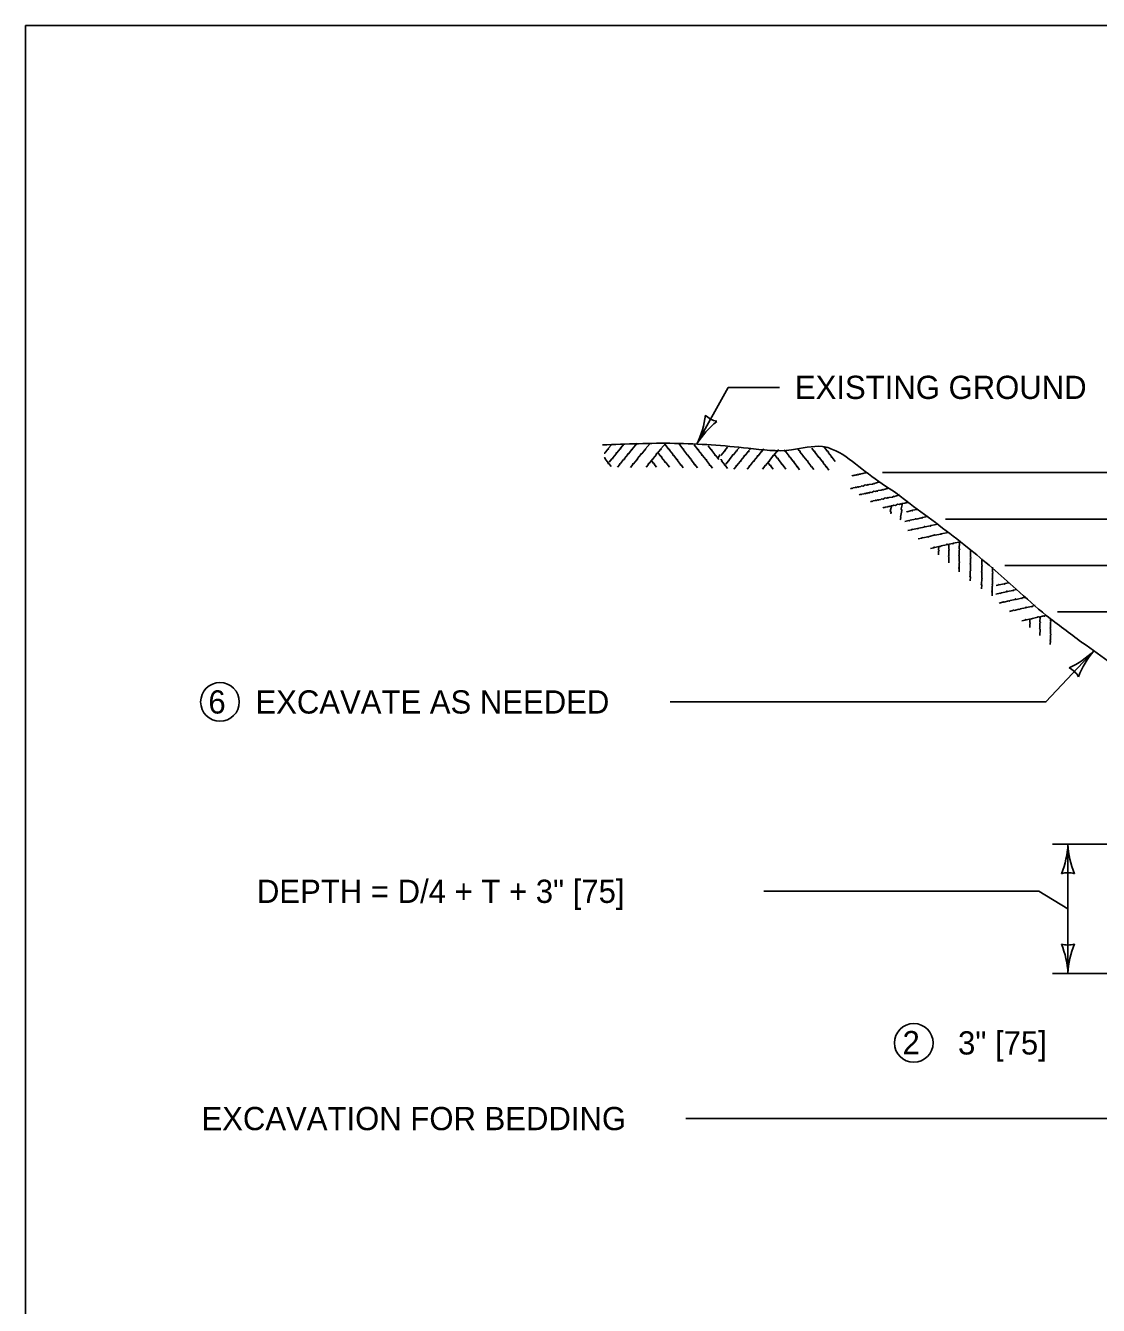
# Model space of a CAD drawing. Extents: x 49991.4 to 50021, y 49987.6 to 50011.4.
# Drawn here: x 49999.384 to 50002.154, y 49995.693 to 49998.999 of the extents above; entities that cross this region are included whole.
import ezdxf

# ---------------------------------------------------------------- set-up
doc = ezdxf.new("R2010")
doc.units = 0
for name, color, linetype in [('Level 1', 7, 'Continuous'), ('Level 2', 7, 'Continuous'), ('Level 3', 7, 'Continuous')]:
    doc.layers.add(name, color=color, linetype=linetype)

msp = doc.modelspace()

# ---------------------------------------------------------------- linework, layer by layer
at = {"layer": 'Level 1'}
for p, q in [((50001.5964, 49997.8446), (50003.795, 49997.8446)), ((50001.7594, 49997.7246), (50003.4766, 49997.7246)), ((50001.9129, 49997.6046), (50003.1822, 49997.6047)), ((50002.0489, 49997.4846), (50003.0064, 49997.4846))]:
    msp.add_line(p, q, dxfattribs=at)
msp.add_lwpolyline([(49999.3835, 49998.9992), (50016.7501, 49998.9992), (50016.7501, 49987.7988), (49999.3835, 49987.7988)], close=True, dxfattribs=at)
for points in [[(50000.8966, 49997.9164), (50000.8884, 49997.9068), (50000.8892, 49997.9052), (50000.8876, 49997.9052), (50000.8791, 49997.8947), (50000.878, 49997.8948)], [(50000.9298, 49997.9191), (50000.9198, 49997.9075), (50000.9206, 49997.9059), (50000.919, 49997.9059), (50000.9105, 49997.8954), (50000.9084, 49997.8955), (50000.9086, 49997.8934), (50000.8998, 49997.8829), (50000.8998, 49997.8808), (50000.8979, 49997.8802), (50000.891, 49997.8715)], [(50000.9626, 49997.9203), (50000.9499, 49997.9055), (50000.9507, 49997.9039), (50000.9491, 49997.9039), (50000.9406, 49997.8935), (50000.9384, 49997.8935), (50000.9387, 49997.8915), (50000.9299, 49997.8809), (50000.9299, 49997.8788), (50000.928, 49997.8782), (50000.9196, 49997.8677), (50000.9176, 49997.8676), (50000.918, 49997.8656), (50000.9119, 49997.8585)], [(50000.9963, 49997.9197), (50000.984, 49997.9052), (50000.9847, 49997.9036), (50000.9831, 49997.9037), (50000.9746, 49997.8932), (50000.9725, 49997.8932), (50000.9727, 49997.8912), (50000.9639, 49997.8806), (50000.9639, 49997.8786), (50000.962, 49997.8779), (50000.9537, 49997.8675), (50000.9517, 49997.8673), (50000.952, 49997.8653), (50000.946, 49997.8582)], [(50001.0366, 49997.9205), (50001.0239, 49997.9057), (50001.0246, 49997.904), (50001.023, 49997.9041), (50001.0145, 49997.8936), (50001.0124, 49997.8936), (50001.0126, 49997.8916), (50001.0039, 49997.881), (50001.0038, 49997.879), (50001.0019, 49997.8783), (50000.9936, 49997.8679), (50000.9915, 49997.8678), (50000.9919, 49997.8657), (50000.9859, 49997.8586)], [(50001.0817, 49997.857), (50001.0764, 49997.8643), (50001.0747, 49997.8639), (50001.0751, 49997.8654), (50001.0668, 49997.8761), (50001.0673, 49997.8781), (50001.0653, 49997.8784), (50001.0569, 49997.8893), (50001.055, 49997.8898), (50001.0548, 49997.8918), (50001.0465, 49997.9023), (50001.0468, 49997.9043), (50001.0448, 49997.9044), (50001.0353, 49997.917)], [(50001.1185, 49997.8571), (50001.1123, 49997.8654), (50001.1106, 49997.865), (50001.111, 49997.8666), (50001.1027, 49997.8772), (50001.1032, 49997.8793), (50001.1012, 49997.8795), (50001.0928, 49997.8905), (50001.0909, 49997.891), (50001.0907, 49997.8929), (50001.0824, 49997.9035), (50001.0827, 49997.9055), (50001.0807, 49997.9056), (50001.0703, 49997.9194)], [(50001.1574, 49997.8557), (50001.1512, 49997.864), (50001.1495, 49997.8636), (50001.1499, 49997.8651), (50001.1416, 49997.8758), (50001.1421, 49997.8779), (50001.1401, 49997.8781), (50001.1318, 49997.889), (50001.1298, 49997.8895), (50001.1296, 49997.8915), (50001.1213, 49997.902), (50001.1216, 49997.904), (50001.1196, 49997.9041), (50001.1104, 49997.9164)], [(50001.1737, 49997.8784), (50001.1659, 49997.8886), (50001.164, 49997.8891), (50001.1638, 49997.8911), (50001.1555, 49997.9016), (50001.1558, 49997.9036), (50001.1537, 49997.9037), (50001.146, 49997.9141)], [(50001.1961, 49997.9099), (50001.1893, 49997.9019), (50001.1901, 49997.9003), (50001.1884, 49997.9003), (50001.18, 49997.8898), (50001.1788, 49997.8899)], [(50001.226, 49997.9088), (50001.2207, 49997.9026), (50001.2215, 49997.901), (50001.2199, 49997.901), (50001.2114, 49997.8905), (50001.2092, 49997.8906), (50001.2095, 49997.8885), (50001.2007, 49997.878), (50001.2007, 49997.8759), (50001.1988, 49997.8753), (50001.1919, 49997.8666)], [(50001.2555, 49997.9061), (50001.2508, 49997.9006), (50001.2516, 49997.899), (50001.25, 49997.899), (50001.2415, 49997.8886), (50001.2393, 49997.8886), (50001.2396, 49997.8866), (50001.2308, 49997.876), (50001.2308, 49997.8739), (50001.2289, 49997.8733), (50001.2205, 49997.8628), (50001.2185, 49997.8627), (50001.2188, 49997.8607), (50001.2128, 49997.8536)], [(50001.2897, 49997.906), (50001.2848, 49997.9003), (50001.2856, 49997.8987), (50001.284, 49997.8988), (50001.2755, 49997.8883), (50001.2734, 49997.8883), (50001.2736, 49997.8863), (50001.2648, 49997.8757), (50001.2648, 49997.8737), (50001.2629, 49997.873), (50001.2546, 49997.8626), (50001.2525, 49997.8625), (50001.2529, 49997.8604), (50001.2469, 49997.8533)], [(50001.3277, 49997.9042), (50001.3248, 49997.9008), (50001.3255, 49997.8991), (50001.3239, 49997.8992), (50001.3154, 49997.8887), (50001.3133, 49997.8887), (50001.3135, 49997.8867), (50001.3047, 49997.8761), (50001.3047, 49997.8741), (50001.3028, 49997.8734), (50001.2945, 49997.863), (50001.2924, 49997.8629), (50001.2928, 49997.8608), (50001.2868, 49997.8537)], [(50001.3826, 49997.8521), (50001.3773, 49997.8594), (50001.3756, 49997.859), (50001.376, 49997.8605), (50001.3677, 49997.8712), (50001.3682, 49997.8733), (50001.3662, 49997.8735), (50001.3578, 49997.8844), (50001.3559, 49997.8849), (50001.3557, 49997.8869), (50001.3474, 49997.8974), (50001.3477, 49997.8994), (50001.3456, 49997.8995), (50001.3425, 49997.9037)], [(50001.4193, 49997.8522), (50001.4132, 49997.8605), (50001.4115, 49997.8601), (50001.4119, 49997.8617), (50001.4036, 49997.8723), (50001.4041, 49997.8744), (50001.4021, 49997.8746), (50001.3937, 49997.8856), (50001.3918, 49997.8861), (50001.3916, 49997.888), (50001.3833, 49997.8986), (50001.3836, 49997.9006), (50001.3815, 49997.9007), (50001.379, 49997.9041)], [(50001.4582, 49997.8508), (50001.4521, 49997.8591), (50001.4504, 49997.8587), (50001.4508, 49997.8602), (50001.4425, 49997.8709), (50001.443, 49997.873), (50001.441, 49997.8732), (50001.4326, 49997.8841), (50001.4307, 49997.8846), (50001.4305, 49997.8866), (50001.4222, 49997.8971), (50001.4225, 49997.8991), (50001.4205, 49997.8992), (50001.4138, 49997.9081)], [(50001.4746, 49997.8735), (50001.4668, 49997.8837), (50001.4648, 49997.8842), (50001.4647, 49997.8862), (50001.4564, 49997.8967), (50001.4567, 49997.8987), (50001.4546, 49997.8988), (50001.4449, 49997.9118)], [(50000.8956, 49997.8602), (50000.8896, 49997.8684), (50000.8878, 49997.868), (50000.8882, 49997.8695), (50000.8799, 49997.8802), (50000.8805, 49997.8823), (50000.8784, 49997.8825), (50000.8779, 49997.8832)], [(50001.0129, 49997.8586), (50001.007, 49997.8661), (50001.0074, 49997.8681), (50001.0053, 49997.8682), (50000.9996, 49997.8758)], [(50001.0462, 49997.8586), (50001.0367, 49997.871), (50001.0348, 49997.8715), (50001.0346, 49997.8734), (50001.0262, 49997.884), (50001.0266, 49997.8859), (50001.0245, 49997.886), (50001.0167, 49997.8965)], [(50001.1765, 49997.8899), (50001.1754, 49997.8899), (50001.1756, 49997.8879), (50001.1724, 49997.8839)], [(50001.1965, 49997.8553), (50001.1905, 49997.8635), (50001.1887, 49997.8631), (50001.1891, 49997.8646), (50001.1808, 49997.8753), (50001.1814, 49997.8774), (50001.1793, 49997.8776), (50001.1788, 49997.8783)], [(50001.3138, 49997.8537), (50001.3079, 49997.8612), (50001.3082, 49997.8632), (50001.3062, 49997.8633), (50001.3005, 49997.8709)], [(50001.3471, 49997.8537), (50001.3376, 49997.8661), (50001.3357, 49997.8666), (50001.3354, 49997.8685), (50001.3271, 49997.8791), (50001.3275, 49997.8811), (50001.3254, 49997.8811), (50001.318, 49997.8911)], [(50001.5539, 49997.8457), (50001.554, 49997.8443), (50001.5494, 49997.8431), (50001.5487, 49997.8423), (50001.548, 49997.8429), (50001.546, 49997.842), (50001.5419, 49997.8415), (50001.5413, 49997.8408), (50001.5405, 49997.8414), (50001.5386, 49997.8405), (50001.5364, 49997.8409), (50001.5339, 49997.8392), (50001.5317, 49997.8397), (50001.5311, 49997.8389), (50001.5284, 49997.8386), (50001.5278, 49997.8378), (50001.527, 49997.8384), (50001.525, 49997.8375), (50001.5242, 49997.8381), (50001.5236, 49997.8374), (50001.5209, 49997.8371), (50001.5203, 49997.8363), (50001.5195, 49997.8369), (50001.5176, 49997.836)], [(50001.5864, 49997.8224), (50001.5867, 49997.8197), (50001.5773, 49997.8172), (50001.5761, 49997.8157), (50001.5746, 49997.8168), (50001.5706, 49997.8151), (50001.5624, 49997.8141), (50001.5612, 49997.8126), (50001.5596, 49997.8138), (50001.5557, 49997.8119), (50001.5514, 49997.8128), (50001.5463, 49997.8095), (50001.542, 49997.8103), (50001.5408, 49997.8089), (50001.5353, 49997.8082), (50001.5341, 49997.8067), (50001.5326, 49997.8079), (50001.5287, 49997.806), (50001.5271, 49997.8072), (50001.5259, 49997.8057), (50001.5204, 49997.8051), (50001.5193, 49997.8036), (50001.5177, 49997.8048), (50001.5137, 49997.8029)], [(50001.609, 49997.8063), (50001.6093, 49997.8035), (50001.5999, 49997.8011), (50001.5987, 49997.7996), (50001.5972, 49997.8008), (50001.5932, 49997.7989), (50001.585, 49997.798), (50001.5838, 49997.7964), (50001.5823, 49997.7977), (50001.5783, 49997.7958), (50001.5741, 49997.7967), (50001.5689, 49997.7933), (50001.5647, 49997.7942), (50001.5635, 49997.7927), (50001.558, 49997.7921), (50001.5568, 49997.7906), (50001.5552, 49997.7918), (50001.5513, 49997.7899), (50001.5497, 49997.7912), (50001.5485, 49997.7896), (50001.5431, 49997.789), (50001.5419, 49997.7875), (50001.5403, 49997.7887), (50001.5364, 49997.7868)], [(50001.638, 49997.7889), (50001.6384, 49997.7861), (50001.6289, 49997.7837), (50001.6277, 49997.7821), (50001.6262, 49997.7833), (50001.6223, 49997.7815), (50001.6141, 49997.7806), (50001.6129, 49997.779), (50001.6113, 49997.7802), (50001.6074, 49997.7784), (50001.6031, 49997.7793), (50001.5979, 49997.7759), (50001.5937, 49997.7768), (50001.5925, 49997.7753), (50001.587, 49997.7746), (50001.5858, 49997.7731), (50001.5843, 49997.7744), (50001.5803, 49997.7725), (50001.5788, 49997.7737), (50001.5776, 49997.7722), (50001.5721, 49997.7715), (50001.5709, 49997.77), (50001.5694, 49997.7712), (50001.5654, 49997.7694)], [(50001.6135, 49997.8034), (50001.6277, 49997.7946), (50001.6676, 49997.7639)], [(50001.6623, 49997.768), (50001.6623, 49997.768), (50001.661, 49997.7676), (50001.6597, 49997.766), (50001.6582, 49997.7673), (50001.6543, 49997.7654), (50001.6461, 49997.7645), (50001.6449, 49997.7629), (50001.6433, 49997.7642), (50001.6394, 49997.7623), (50001.6351, 49997.7632), (50001.6299, 49997.7598), (50001.6257, 49997.7607), (50001.6245, 49997.7592), (50001.619, 49997.7586), (50001.6178, 49997.7571), (50001.6163, 49997.7583), (50001.6123, 49997.7565), (50001.6108, 49997.7576), (50001.6096, 49997.7561), (50001.6041, 49997.7555), (50001.6029, 49997.754), (50001.6014, 49997.7552), (50001.5974, 49997.7533)], [(50001.6206, 49997.7598), (50001.6167, 49997.7455), (50001.6186, 49997.7415), (50001.6178, 49997.7382)], [(50001.6484, 49997.7651), (50001.6445, 49997.7508), (50001.6463, 49997.7468), (50001.6428, 49997.7298), (50001.6443, 49997.7286), (50001.6434, 49997.7243), (50001.6424, 49997.723)], [(50001.6863, 49997.7496), (50001.6739, 49997.7472), (50001.6735, 49997.7455), (50001.6723, 49997.7465), (50001.6591, 49997.7435), (50001.6583, 49997.7443)], [(50001.714, 49997.7311), (50001.6989, 49997.7282), (50001.6986, 49997.7265), (50001.6973, 49997.7275), (50001.6841, 49997.7246), (50001.6826, 49997.7259), (50001.6814, 49997.7242), (50001.668, 49997.7214), (50001.6667, 49997.7198), (50001.6648, 49997.7205), (50001.654, 49997.7179)], [(50001.7404, 49997.7117), (50001.7213, 49997.708), (50001.7209, 49997.7062), (50001.7197, 49997.7072), (50001.7065, 49997.7044), (50001.7048, 49997.7057), (50001.7038, 49997.704), (50001.6903, 49997.7011), (50001.689, 49997.6995), (50001.6872, 49997.7002), (50001.674, 49997.6972), (50001.6724, 49997.6984), (50001.6715, 49997.6965), (50001.6623, 49997.6948)], [(50001.7665, 49997.6903), (50001.7478, 49997.6865), (50001.7474, 49997.6849), (50001.7462, 49997.6859), (50001.733, 49997.683), (50001.7313, 49997.6843), (50001.7303, 49997.6826), (50001.7168, 49997.6798), (50001.7155, 49997.6782), (50001.7136, 49997.6788), (50001.7006, 49997.6758), (50001.6989, 49997.6769), (50001.6979, 49997.6752), (50001.6888, 49997.6733)], [(50001.7985, 49997.6658), (50001.7794, 49997.6621), (50001.7789, 49997.6604), (50001.7777, 49997.6614), (50001.7645, 49997.6585), (50001.7628, 49997.6598), (50001.7618, 49997.6581), (50001.7484, 49997.6552), (50001.747, 49997.6537), (50001.7451, 49997.6543), (50001.7321, 49997.6514), (50001.7304, 49997.6526), (50001.7294, 49997.6507), (50001.7203, 49997.6489)], [(50001.7415, 49997.6321), (50001.7415, 49997.6416), (50001.7431, 49997.6429), (50001.7415, 49997.6443), (50001.7418, 49997.6538)], [(50001.7676, 49997.6114), (50001.7678, 49997.627), (50001.7667, 49997.6286), (50001.7677, 49997.6302), (50001.7677, 49997.6437), (50001.7692, 49997.6449), (50001.7676, 49997.6463), (50001.768, 49997.6594)], [(50001.7944, 49997.5881), (50001.7948, 49997.5971), (50001.7932, 49997.5978), (50001.7944, 49997.5987), (50001.7946, 49997.6123), (50001.7962, 49997.6135), (50001.7948, 49997.615), (50001.795, 49997.6288), (50001.7939, 49997.6304), (50001.7949, 49997.632), (50001.795, 49997.6454), (50001.7964, 49997.6468), (50001.7949, 49997.6481), (50001.7953, 49997.6639)], [(50001.8233, 49997.5653), (50001.8236, 49997.5756), (50001.822, 49997.5764), (50001.8233, 49997.5774), (50001.8234, 49997.5908), (50001.8251, 49997.5922), (50001.8236, 49997.5936), (50001.8239, 49997.6074), (50001.8227, 49997.609), (50001.8237, 49997.6106), (50001.8238, 49997.6241), (50001.8253, 49997.6254), (50001.8238, 49997.6268), (50001.8242, 49997.644)], [(50001.8525, 49997.5447), (50001.8528, 49997.5551), (50001.8513, 49997.5558), (50001.8525, 49997.5567), (50001.8527, 49997.5703), (50001.8544, 49997.5716), (50001.8529, 49997.573), (50001.8532, 49997.5867), (50001.8519, 49997.5883), (50001.853, 49997.59), (50001.853, 49997.6034), (50001.8545, 49997.6048), (50001.853, 49997.6061), (50001.8534, 49997.6215)], [(50001.8803, 49997.5552), (50001.8806, 49997.5681), (50001.8794, 49997.5697), (50001.8805, 49997.5713), (50001.8805, 49997.5847), (50001.882, 49997.5861), (50001.8804, 49997.5875), (50001.8808, 49997.6004)], [(50001.8796, 49997.5267), (50001.88, 49997.5368), (50001.8783, 49997.5376), (50001.8796, 49997.5386), (50001.8797, 49997.5521), (50001.8815, 49997.5534), (50001.88, 49997.5548), (50001.88, 49997.5557)], [(50001.9426, 49997.5427), (50001.9346, 49997.5411), (50001.9342, 49997.5394), (50001.9329, 49997.5403), (50001.9198, 49997.5374), (50001.9181, 49997.5388), (50001.917, 49997.537), (50001.9036, 49997.5343), (50001.9023, 49997.5326), (50001.9004, 49997.5333), (50001.8896, 49997.5308)], [(50001.8971, 49997.5552), (50001.8962, 49997.5558), (50001.8951, 49997.5542), (50001.8901, 49997.553)], [(50001.9229, 49997.5602), (50001.9126, 49997.5582), (50001.9122, 49997.5564), (50001.9109, 49997.5575), (50001.8978, 49997.5545), (50001.8969, 49997.5553)], [(50001.964, 49997.5222), (50001.9569, 49997.5208), (50001.9565, 49997.5191), (50001.9553, 49997.5201), (50001.9422, 49997.5172), (50001.9404, 49997.5186), (50001.9394, 49997.5168), (50001.9259, 49997.514), (50001.9246, 49997.5123), (50001.9228, 49997.5131), (50001.9097, 49997.51), (50001.908, 49997.5112), (50001.907, 49997.5095), (50001.8979, 49997.5076)], [(50001.9907, 49997.5009), (50001.9833, 49997.4995), (50001.983, 49997.4977), (50001.9818, 49997.4988), (50001.9686, 49997.4958), (50001.967, 49997.4971), (50001.9659, 49997.4955), (50001.9524, 49997.4926), (50001.9511, 49997.4911), (50001.9492, 49997.4917), (50001.9363, 49997.4887), (50001.9346, 49997.4899), (50001.9336, 49997.488), (50001.9244, 49997.4862)], [(50002.0194, 49997.4759), (50002.015, 49997.475), (50002.0145, 49997.4732), (50002.0133, 49997.4743), (50002.0001, 49997.4714), (50001.9985, 49997.4727), (50001.9974, 49997.471), (50001.9839, 49997.4681), (50001.9827, 49997.4666), (50001.9807, 49997.4672), (50001.9678, 49997.4642), (50001.9661, 49997.4654), (50001.9651, 49997.4635), (50001.956, 49997.4617)], [(50001.9771, 49997.4449), (50001.9771, 49997.4545), (50001.9786, 49997.4559), (50001.9771, 49997.4572), (50001.9774, 49997.4667)], [(50002.0032, 49997.4242), (50002.0035, 49997.4399), (50002.0023, 49997.4414), (50002.0032, 49997.4431), (50002.0033, 49997.4566), (50002.0049, 49997.4579), (50002.0032, 49997.4592), (50002.0036, 49997.4716)], [(50002.03, 49997.4009), (50002.0304, 49997.4099), (50002.0288, 49997.4107), (50002.0301, 49997.4116), (50002.0302, 49997.4251), (50002.0319, 49997.4265), (50002.0305, 49997.4279), (50002.0307, 49997.4416), (50002.0295, 49997.4432), (50002.0306, 49997.4449), (50002.0306, 49997.4583), (50002.0321, 49997.4597), (50002.0305, 49997.461), (50002.0307, 49997.4663)]]:
    msp.add_lwpolyline(points, dxfattribs=at)
for points in [[(50000.8731, 49997.9159), (50001.0592, 49997.9201), (50001.2495, 49997.9075), (50001.3616, 49997.9032), (50001.442, 49997.9117), (50001.4759, 49997.9011), (50001.5432, 49997.8542), (50001.6135, 49997.8034)], [(50001.6676, 49997.7639), (50001.816, 49997.6515), (50001.9419, 49997.5436), (50002.0197, 49997.4756), (50002.1106, 49997.407), (50002.113, 49997.4052)], [(50002.113, 49997.4052), (50002.2614, 49997.2928), (50002.2697, 49997.2855)]]:
    msp.add_spline(points, degree=3, dxfattribs=at)
at = {"layer": 'Level 2'}
for centre in [(49999.8855, 49997.2522), (50001.6774, 49996.3715)]:
    msp.add_circle(centre, 0.05, dxfattribs=at)
at = {"layer": 'Level 3'}
for p, q in [((50001.1171, 49997.9186), (50001.1982, 49998.0648)), ((50001.3304, 49998.0648), (50001.1982, 49998.0648)), ((50001.1982, 49998.0648), (50001.3304, 49998.0648)), ((50002.0355, 49996.8846), (50002.3003, 49996.8846)), ((50002.0755, 49996.5509), (50002.0755, 49996.8846)), ((50002.0007, 49996.7631), (50001.2905, 49996.7631)), ((50002.0755, 49996.7178), (50002.0007, 49996.7631)), ((50002.0355, 49996.5509), (50002.8589, 49996.5509)), ((50002.6251, 49996.1761), (50001.0883, 49996.1761))]:
    msp.add_line(p, q, dxfattribs=at)
msp.add_lwpolyline([(50001.0483, 49997.2522), (50002.0187, 49997.2522), (50002.1426, 49997.3844)], dxfattribs=at)
for centre, radius, start, end in [((50000.9184, 49998.0184), 0.2223, 333.3425, 353.526), ((50001.315, 49997.7957), 0.233, 128.9048, 148.1547), ((50001.1793, 49998.0308), 0.0548, 223.1208, 258.8432), ((50001.9868, 49997.543), 0.2223, 294.3067, 314.4902), ((50002.3203, 49997.2336), 0.233, 139.678, 158.9279), ((50002.0549, 49997.2908), 0.0548, 28.9895, 64.7119), ((50001.8534, 49996.8938), 0.2223, 337.456, 357.6395), ((50002.3082, 49996.8961), 0.233, 182.8273, 202.0772), ((50002.0755, 49996.7564), 0.0548, 72.1388, 107.8612), ((50002.0755, 49996.6791), 0.0548, 252.1388, 287.8612), ((50001.8428, 49996.5394), 0.233, 2.8273, 22.0772), ((50002.2977, 49996.5418), 0.2223, 157.456, 177.6395)]:
    msp.add_arc(centre, radius, start, end, dxfattribs=at)

# ---------------------------------------------------------------- texts
at = {"layer": 'Level 2'}
for s, p in [('EXISTING GROUND', (50001.3704, 49998.0348)), ('6', (49999.8556, 49997.2222)), ('EXCAVATE AS NEEDED', (49999.9771, 49997.2222)), ('DEPTH = D/4 + T + 3" [75]', (49999.981, 49996.7331)), ('2', (50001.6483, 49996.3422)), ('3" [75]', (50001.7917, 49996.3415)), ('EXCAVATION FOR BEDDING', (49999.8377, 49996.1461))]:
    msp.add_text(s, height=0.06, dxfattribs=at).set_placement(p)

doc.saveas('drawing.dxf')
